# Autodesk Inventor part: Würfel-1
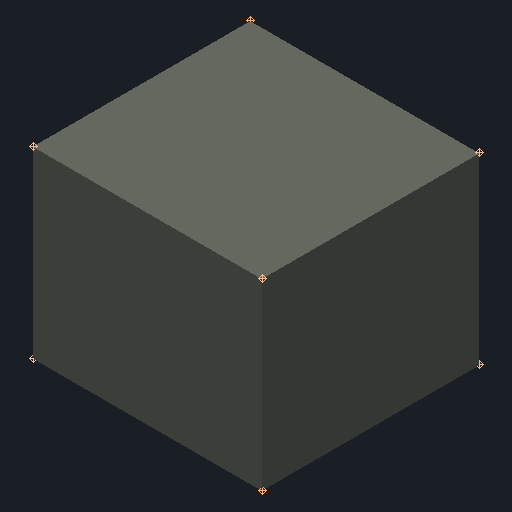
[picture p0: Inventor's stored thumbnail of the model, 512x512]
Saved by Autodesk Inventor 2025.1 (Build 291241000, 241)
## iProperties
Company: Ed. Züblin AG
Created: 2021-07
Part Number: Würfel-1
Material: Stahlbeton C30/37
Document SubType Name: Modeling
Designer: Eimannsmir
Mass: 3.70653 g
Surface Area: 7.83735 cm^2
Volume: 1.48261 cm^3
Density: 2.5 g/cm^3
Appearance: Beton C30/37
z_Bereich: Tunnelbau
z_Direktion: Tief- und Tunnelbau
z_Konzerneinheit: Zentrale Technik
z_Matchkey: =<z_Matchkey_010>_<z_Matchkey_020>_<z_Matchkey_030>_<z_Matchkey_040>_<z_Matchkey_050>_<z_Matchkey_060>_<z_Matchkey_070>_<z_Matchkey_080>_<z_Matchkey_090>_<z_Mat
cpiComponentType: Attribut
cpiFitMatchkey: =<z_Matchkey>
z_Matchkey_010: xxxxx
z_Matchkey_020: 5DTUB
z_Matchkey_030: xxx
z_Matchkey_040: xxx
z_Matchkey_050: xxx
z_Matchkey_060: xxx
z_Matchkey_070: xxx
z_Matchkey_080: xxx
z_Matchkey_090: xxx
z_Matchkey_100: xxx
z_Matchkey_110: xxx
z_Matchkey_120: xxxxxxx
z_Matchkey_130: xxxx
z_Matchkey_140: xxxx
DocNumber: Würfel-1.ipt
Folder: Übung\
VDS_Category: Konstruktion
Betondeckung: ND
Betonstahlguete: ND
Bewehrungsgehalt: ND
Druckfestigkeitsklasse: ND
Expositionsklasse_X: ND
Expositionsklasse_XA: ND
Expositionsklasse_XC: ND
Expositionsklasse_XD: ND
Expositionsklasse_XF: ND
Expositionsklasse_XM: ND
Expositionsklasse_XS: ND
Feuchtigkeitsklasse: ND
Groesstkorn: ND
Herstellungsort: ND
Luftporenbeton: ND
Rohdichte: ND
Sichtbetonklasse: ND
Unbewehrter_Beton: ND
Wasserzementwert_max: ND
WU_Beton: ND
Zusatzmittel: ND
010_Eigentuemer: ND
020_Autor: ND
030_Projektnummer: ND
040_Bereich: ND
050_Vertragspartner: ND
060_Gewerk: ND
070_Bauwerk: ND
080_Bauwerksnummer: ND
090_Bezeichnung: ND
100_Gruppe: ND
110_Element: ND
120_Elementtyp: ND
130_Identifikationsnummer: ND
140_Position_1: ND
150_Position_2: ND
160_PUID: ND
170_Hauptmaterialitaet: ND
171_Materialindikator_1: ND
172_Materialindikator_2: ND
Dicke: ND
Flaeche: ND
Streckenachse: ND
Streckenkilometer_Anfang: ND
Streckenkilometer_Ende: ND
Tunnelachse: ND
Tunnelmeter_Anfang: ND
Tunnelmeter_Ende: ND
4D_Vorgangs_ID: ND
Bauphase_Abgebrochen: ND
Bauphase_Erstellt: ND
Status: ND
Author: Eimannsmir
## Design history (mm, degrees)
sketch "Skizze3"
  geometry: L1 (-5.887, -5.786)-(6.609, -5.786); L2 (6.609, -5.786)-(6.609, 6.079); L3 (6.609, 6.079)-(-5.887, 6.079); L4 (-5.887, 6.079)-(-5.887, -5.786); 1 further point
  constraints: 8 end point, 2 parallel, 1 horizontal, 1 perpendicular
extrude "Extrusion3" new body sketch "Skizze3" stored distance "d4" = 10; taper "d5" = 0 deg
workpoint "Arbeitspunkt1"
workpoint "Arbeitspunkt2"
workpoint "Arbeitspunkt3"
workpoint "Arbeitspunkt4"
workpoint "Arbeitspunkt5"
workpoint "Arbeitspunkt6"
workpoint "Arbeitspunkt7"
workpoint "Arbeitspunkt8"
node "Volumenkörper3"
node "Volumenkörpern"
node "Oberflächenkörpern"
